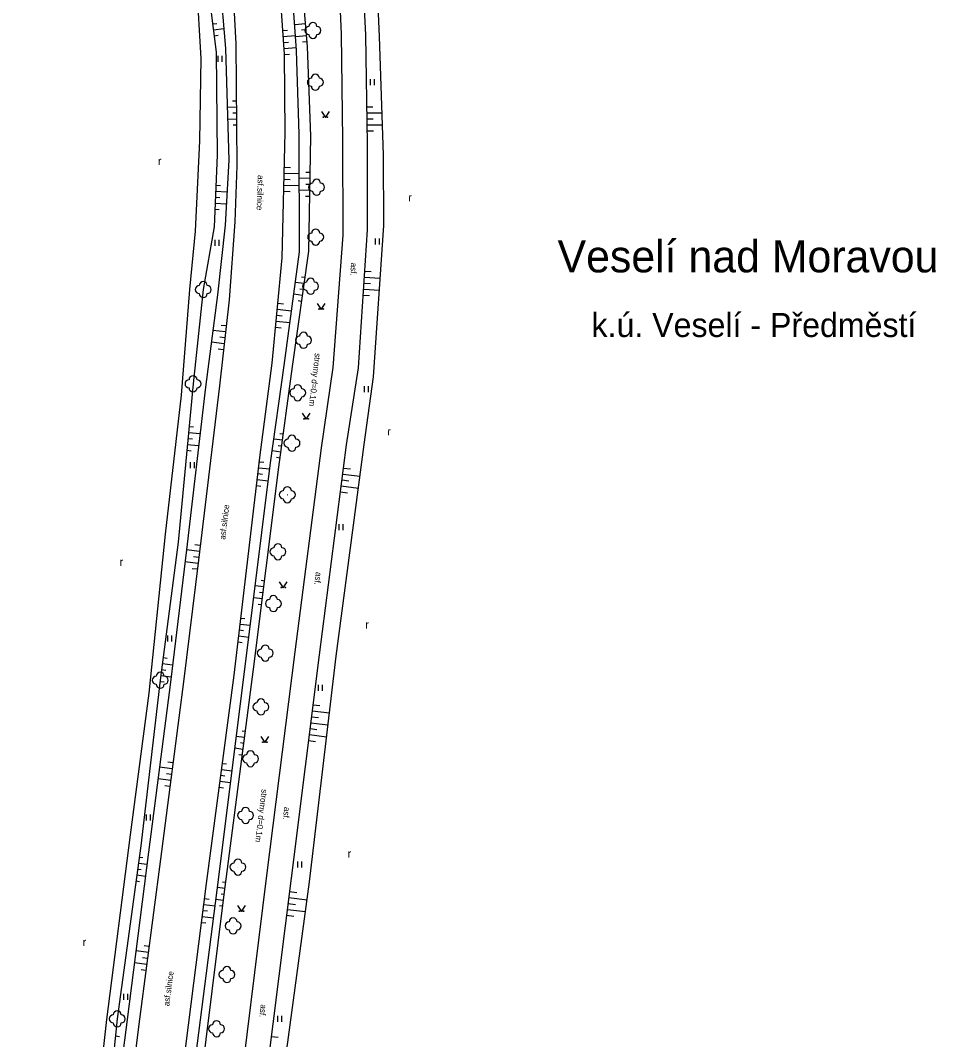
# Model space of a CAD drawing. Extents: x -544674 to -541478, y -1199076 to -1195527.
# Drawn here: x -543649.7 to -543535.3, y -1196121 to -1195993.6 of the extents above; entities that cross this region are included whole.
import ezdxf

# ---------------------------------------------------------------- set-up
doc = ezdxf.new("R2010")
doc.units = 0
for name, color, linetype in [('NÁZEV_K_Ú', 7, 'Continuous'), ('NÁZVY_SÍDEL_JEDNOTKY', 7, 'Continuous'), ('POMOC_POPIS', 7, 'Continuous'), ('ROZHRANÍ_PLOCH', 7, 'Continuous'), ('VÝŠKOPIS', 7, 'Continuous'), ('ZELEŇ', 7, 'Continuous'), ('ZN_KULTUR', 7, 'Continuous')]:
    doc.layers.add(name, color=color, linetype=linetype)

msp = doc.modelspace()

# ---------------------------------------------------------------- linework, layer by layer
at = {"layer": 'ROZHRANÍ_PLOCH'}
for points in [[(-543619.64, -1196131.22), (-543615.81, -1196100.77), (-543612.31, -1196072.88), (-543608.9, -1196046.62), (-543607.43, -1196037.02), (-543606.28, -1196019.77), (-543606.3, -1196009), (-543606.5, -1195995.43), (-543607.06, -1195984.44), (-543608.01, -1195967.52), (-543610.49, -1195940.94), (-543612.66, -1195916.66), (-543613.72, -1195904.08), (-543614, -1195894.09), (-543612.96, -1195887.23), (-543612.45, -1195879.29), (-543612.44, -1195876.36), (-543611.47, -1195876.49), (-543610.1, -1195878.26), (-543608.46, -1195876.99), (-543612.9, -1195869.72), (-543612.98, -1195867.19)], [(-543632.41, -1196211.07), (-543630.37, -1196193.32), (-543624.96, -1196151.17), (-543622.81, -1196132.43), (-543618.85, -1196100.43), (-543615.34, -1196072.49), (-543612.05, -1196046.99), (-543610.57, -1196036.97), (-543609.35, -1196020.42), (-543609.38, -1196008.52), (-543609.53, -1195995.3), (-543610, -1195984.65), (-543611.08, -1195968.31), (-543613.38, -1195942.54), (-543615.71, -1195916.87), (-543616.79, -1195903.73), (-543617.14, -1195895.44), (-543615.68, -1195885.08), (-543615.46, -1195880.81), (-543615.95, -1195868.23)], [(-543632.46, -1195882.95), (-543630.66, -1195904.04), (-543629.59, -1195915.71), (-543627.44, -1195938.51), (-543625.46, -1195962.01), (-543624.21, -1195975.84), (-543623.14, -1195988.77), (-543622.74, -1195996.52), (-543622.61, -1196011.77), (-543622.88, -1196018.77), (-543623.58, -1196028.52), (-543624.79, -1196039.27), (-543627.41, -1196061.04), (-543629.27, -1196076.23), (-543632.15, -1196098.41), (-543634.76, -1196118.38), (-543637.1, -1196136.86), (-543638.96, -1196152.81), (-543641.47, -1196173.25), (-543643.67, -1196191.48), (-543644.99, -1196202.76)], [(-543639.09, -1196203.64), (-543635.02, -1196171.2), (-543630.55, -1196134.22), (-543626.42, -1196101.45), (-543622.95, -1196075.4), (-543619.74, -1196048.22), (-543618.21, -1196036.42), (-543616.96, -1196023.24), (-543616.56, -1196007.59), (-543616.68, -1195997.82), (-543617.53, -1195985.22), (-543618.61, -1195971.27), (-543620.62, -1195946.9), (-543623.05, -1195920.62), (-543624.43, -1195906.58), (-543625.23, -1195895.93), (-543626.38, -1195882.3)]]:
    msp.add_lwpolyline(points, dxfattribs=at)
at = {"layer": 'VÝŠKOPIS'}
for points in [[(-543637.68, -1196204.91), (-543633.55, -1196170.77), (-543629.08, -1196133.41), (-543625.09, -1196102.26), (-543621.67, -1196075.01), (-543618.41, -1196048.88), (-543616.7, -1196036.73), (-543614.81, -1196022.52), (-543614.82, -1196007.8), (-543615.15, -1195997.35), (-543616.06, -1195985.01), (-543617.47, -1195971.56), (-543619.73, -1195946.13), (-543622.24, -1195919.83), (-543623.14, -1195907.11), (-543624.18, -1195895.5), (-543625.31, -1195882.76)], [(-543637.05, -1196204.96), (-543632.44, -1196170.19), (-543627.94, -1196133.03), (-543624.22, -1196102.84), (-543620.55, -1196074.64), (-543617.37, -1196049.43), (-543615.66, -1196036.82), (-543613.64, -1196022.43), (-543613.38, -1196008.04), (-543613.8, -1195996.84), (-543614.79, -1195985), (-543616.24, -1195972.22), (-543618.58, -1195945.75), (-543620.93, -1195921.24), (-543621.68, -1195907.9), (-543622.76, -1195895.51), (-543624.24, -1195883.03)], [(-543633.79, -1195883.63), (-543632.32, -1195903.25), (-543630.88, -1195916.7), (-543629.01, -1195937.51), (-543627.31, -1195961.18), (-543625.83, -1195976.22), (-543624.72, -1195988.72), (-543624.05, -1195997.08), (-543623.61, -1196011.03), (-543624.09, -1196019.16), (-543625.02, -1196027.87), (-543626.53, -1196039.42), (-543628.92, -1196059.75), (-543630.9, -1196076.27), (-543633.64, -1196097.53), (-543636.3, -1196118.46), (-543638.55, -1196135.87), (-543640.73, -1196153.47), (-543642.99, -1196172.25), (-543645.26, -1196191.46), (-543646.43, -1196201.58)], [(-543635.11, -1195884.59), (-543633.71, -1195902.59), (-543632.22, -1195917.58), (-543630.51, -1195936.95), (-543628.32, -1195960.9), (-543627.16, -1195976.56), (-543626.29, -1195988.96), (-543625.18, -1195997.54), (-543625.08, -1196010.41), (-543625.45, -1196019.37), (-543626.81, -1196027.23), (-543628.09, -1196039), (-543629.96, -1196058.78), (-543632.18, -1196076.05), (-543634.6, -1196096.72), (-543637.55, -1196118.36), (-543639.29, -1196135.15), (-543642.06, -1196154.03), (-543643.93, -1196171.42), (-543646.59, -1196191.4), (-543647.93, -1196200.94)], [(-543625.64, -1195994.02), (-543625.1, -1195993.95)], [(-543625.54, -1195994.77), (-543624.25, -1195994.6)], [(-543616.88, -1195994.84), (-543616.27, -1195994.8)], [(-543614.04, -1195994.03), (-543615.39, -1195994.14)], [(-543613.97, -1195994.77), (-543614.52, -1195994.82)], [(-543625.44, -1195995.51), (-543624.94, -1195995.44)], [(-543616.83, -1195995.59), (-543615.29, -1195995.48)], [(-543616.78, -1195996.33), (-543616.16, -1195996.29)], [(-543613.91, -1195995.52), (-543615.28, -1195995.64)], [(-543613.85, -1195996.27), (-543614.4, -1195996.32)], [(-543616.73, -1195997.08), (-543615.18, -1195996.98)], [(-543616.68, -1195997.83), (-543616.06, -1195997.82)], [(-543622.68, -1196003.69), (-543623.14, -1196003.69)], [(-543622.67, -1196004.44), (-543623.82, -1196004.45)], [(-543622.67, -1196005.19), (-543623.12, -1196005.19)], [(-543606.37, -1196004.4), (-543605.62, -1196004.39)], [(-543606.36, -1196005.15), (-543604.48, -1196005.12)], [(-543622.66, -1196005.94), (-543623.77, -1196005.95)], [(-543606.35, -1196005.9), (-543605.59, -1196005.89)], [(-543606.33, -1196006.65), (-543604.43, -1196006.62)], [(-543622.65, -1196006.69), (-543623.09, -1196006.69)], [(-543606.32, -1196007.4), (-543605.56, -1196007.39)], [(-543616.69, -1196012.68), (-543614.82, -1196012.73)], [(-543616.67, -1196011.93), (-543615.93, -1196011.95)], [(-543613.46, -1196012.59), (-543614, -1196012.58)], [(-543625.24, -1196014.19), (-543624.66, -1196014.21)], [(-543616.73, -1196014.18), (-543614.82, -1196014.23)], [(-543616.71, -1196013.43), (-543615.95, -1196013.45)], [(-543613.48, -1196013.34), (-543614.82, -1196013.31)], [(-543613.49, -1196014.09), (-543614.02, -1196014.08)], [(-543625.27, -1196014.94), (-543623.84, -1196015)], [(-543616.75, -1196014.93), (-543615.97, -1196014.95)], [(-543613.5, -1196014.84), (-543614.82, -1196014.81)], [(-543613.52, -1196015.59), (-543614.04, -1196015.58)], [(-543625.33, -1196016.44), (-543623.93, -1196016.5)], [(-543625.3, -1196015.69), (-543624.73, -1196015.71)], [(-543625.36, -1196017.19), (-543624.81, -1196017.21)], [(-543614.1, -1196025.73), (-543614.55, -1196025.67)], [(-543606.67, -1196025.66), (-543604.7, -1196025.79)], [(-543606.62, -1196024.91), (-543605.83, -1196024.96)], [(-543614.21, -1196026.47), (-543615.32, -1196026.32)], [(-543606.72, -1196026.4), (-543605.93, -1196026.46)], [(-543614.42, -1196027.96), (-543615.51, -1196027.8)], [(-543614.31, -1196027.22), (-543614.75, -1196027.15)], [(-543606.82, -1196027.9), (-543606.04, -1196027.95)], [(-543606.77, -1196027.15), (-543604.8, -1196027.28)], [(-543617.5, -1196028.94), (-543616.78, -1196029.01)], [(-543614.52, -1196028.7), (-543614.96, -1196028.64)], [(-543617.64, -1196030.44), (-543616.94, -1196030.5)], [(-543617.57, -1196029.69), (-543615.79, -1196029.86)], [(-543623.94, -1196031.76), (-543624.57, -1196031.69)], [(-543617.78, -1196031.93), (-543617.1, -1196031.99)], [(-543617.71, -1196031.18), (-543615.98, -1196031.35)], [(-543624.03, -1196032.5), (-543625.6, -1196032.33)], [(-543624.11, -1196033.25), (-543624.75, -1196033.18)], [(-543624.2, -1196033.99), (-543625.8, -1196033.81)], [(-543624.28, -1196034.74), (-543624.93, -1196034.67)], [(-543628.59, -1196044.33), (-543628.01, -1196044.38)], [(-543628.73, -1196045.82), (-543628.16, -1196045.87)], [(-543628.66, -1196045.07), (-543627.21, -1196045.21)], [(-543616.91, -1196046.05), (-543617.99, -1196045.9)], [(-543616.81, -1196045.3), (-543617.24, -1196045.25)], [(-543628.88, -1196047.31), (-543628.31, -1196047.37)], [(-543628.81, -1196046.57), (-543627.39, -1196046.7)], [(-543617.11, -1196047.53), (-543618.2, -1196047.39)], [(-543617.01, -1196046.79), (-543617.45, -1196046.73)], [(-543617.21, -1196048.28), (-543617.65, -1196048.22)], [(-543619.89, -1196049.48), (-543618.5, -1196049.64)], [(-543619.8, -1196048.73), (-543619.25, -1196048.8)], [(-543609.28, -1196049.52), (-543608.42, -1196049.63)], [(-543620.06, -1196050.97), (-543618.69, -1196051.13)], [(-543619.98, -1196050.22), (-543619.42, -1196050.29)], [(-543609.47, -1196051.01), (-543608.61, -1196051.12)], [(-543609.37, -1196050.27), (-543607.23, -1196050.55)], [(-543620.15, -1196051.71), (-543619.6, -1196051.78)], [(-543609.66, -1196052.5), (-543608.81, -1196052.61)], [(-543609.57, -1196051.75), (-543607.43, -1196052.03)], [(-543627.28, -1196059.95), (-543628.92, -1196059.75)], [(-543627.19, -1196059.2), (-543627.85, -1196059.12)], [(-543627.46, -1196061.44), (-543629.1, -1196061.24)], [(-543627.37, -1196060.69), (-543628.02, -1196060.61)], [(-543627.55, -1196062.18), (-543628.2, -1196062.1)], [(-543619.16, -1196063.65), (-543619.59, -1196063.59)], [(-543619.26, -1196064.39), (-543620.33, -1196064.26)], [(-543619.35, -1196065.14), (-543619.78, -1196065.08)], [(-543619.45, -1196065.88), (-543620.51, -1196065.75)], [(-543619.54, -1196066.63), (-543619.97, -1196066.57)], [(-543622.2, -1196069.02), (-543620.94, -1196069.17)], [(-543622.11, -1196068.28), (-543621.6, -1196068.33)], [(-543622.28, -1196069.76), (-543621.78, -1196069.82)], [(-543622.46, -1196071.25), (-543621.96, -1196071.31)], [(-543622.37, -1196070.51), (-543621.13, -1196070.66)], [(-543631.91, -1196073.97), (-543630.64, -1196074.13)], [(-543631.82, -1196073.22), (-543631.31, -1196073.29)], [(-543632.01, -1196074.71), (-543631.5, -1196074.78)], [(-543632.2, -1196076.2), (-543631.68, -1196076.26)], [(-543632.1, -1196075.46), (-543630.82, -1196075.62)], [(-543613.09, -1196079.11), (-543612.25, -1196079.22)], [(-543613.19, -1196079.86), (-543611.06, -1196080.12)], [(-543613.37, -1196081.35), (-543611.24, -1196081.61)], [(-543613.28, -1196080.6), (-543612.43, -1196080.71)], [(-543621.66, -1196083.19), (-543622.68, -1196083.06)], [(-543621.57, -1196082.44), (-543621.97, -1196082.39)], [(-543613.56, -1196082.83), (-543611.41, -1196083.1)], [(-543613.47, -1196082.09), (-543612.61, -1196082.2)], [(-543621.76, -1196083.93), (-543622.16, -1196083.88)], [(-543613.65, -1196083.58), (-543612.79, -1196083.69)], [(-543621.86, -1196084.68), (-543622.87, -1196084.54)], [(-543621.95, -1196085.42), (-543622.36, -1196085.37)], [(-543630.68, -1196087.1), (-543632.27, -1196086.89)], [(-543630.58, -1196086.36), (-543631.22, -1196086.27)], [(-543624.42, -1196086.44), (-543623.9, -1196086.51)], [(-543630.78, -1196087.84), (-543631.41, -1196087.76)], [(-543624.62, -1196087.92), (-543624.1, -1196087.99)], [(-543624.52, -1196087.18), (-543623.22, -1196087.35)], [(-543630.87, -1196088.59), (-543632.46, -1196088.38)], [(-543630.97, -1196089.33), (-543631.61, -1196089.25)], [(-543624.82, -1196089.41), (-543624.29, -1196089.48)], [(-543624.72, -1196088.67), (-543623.41, -1196088.84)], [(-543634.8, -1196098.15), (-543634.37, -1196098.21)], [(-543635, -1196099.64), (-543634.57, -1196099.7)], [(-543634.9, -1196098.89), (-543633.83, -1196099.04)], [(-543635.1, -1196100.38), (-543634.02, -1196100.53)], [(-543635.2, -1196101.12), (-543634.77, -1196101.18)], [(-543624.12, -1196102.06), (-543625.05, -1196101.94)], [(-543624.02, -1196101.32), (-543624.4, -1196101.27)], [(-543626.66, -1196103.32), (-543626.09, -1196103.39)], [(-543624.31, -1196103.55), (-543625.24, -1196103.43)], [(-543624.22, -1196102.8), (-543624.59, -1196102.76)], [(-543616.11, -1196103.19), (-543613.84, -1196103.48)], [(-543616.02, -1196102.45), (-543615.11, -1196102.56)], [(-543626.75, -1196104.06), (-543625.34, -1196104.24)], [(-543624.4, -1196104.29), (-543624.77, -1196104.25)], [(-543616.3, -1196104.68), (-543614.04, -1196104.96)], [(-543616.21, -1196103.94), (-543615.3, -1196104.05)], [(-543626.94, -1196105.55), (-543625.53, -1196105.73)], [(-543626.84, -1196104.81), (-543626.28, -1196104.88)], [(-543616.4, -1196105.42), (-543615.49, -1196105.54)], [(-543627.03, -1196106.3), (-543626.47, -1196106.37)], [(-543633.58, -1196109.33), (-543634.19, -1196109.25)], [(-543633.67, -1196110.07), (-543635.21, -1196109.87)], [(-543633.77, -1196110.82), (-543634.38, -1196110.74)], [(-543633.87, -1196111.56), (-543635.4, -1196111.36)], [(-543633.97, -1196112.3), (-543634.58, -1196112.22)], [(-543637.77, -1196120.5), (-543637.29, -1196120.55)], [(-543618.3, -1196120.55), (-543617.45, -1196120.66)]]:
    msp.add_lwpolyline(points, dxfattribs=at)
at = {"layer": 'ZELEŇ'}
for points in [[(-543637.49, -1195885.85), (-543636.25, -1195900.75), (-543634.27, -1195918.95), (-543632.55, -1195936.22), (-543630.06, -1195959.48), (-543628.32, -1195978.08), (-543627.64, -1195989.06), (-543627.13, -1195998.35), (-543627.3, -1196008.65), (-543627.81, -1196019.91), (-543628.52, -1196027.23), (-543629.59, -1196040.43), (-543631.56, -1196057.77), (-543633.61, -1196077.67), (-543635.95, -1196095.36), (-543638.88, -1196118.45), (-543640.59, -1196133.76), (-543643.14, -1196154.34), (-543645.07, -1196170.53), (-543648, -1196190.91), (-543649.65, -1196200.28)], [(-543620.94, -1196214.98), (-543624.31, -1196211.9), (-543626.03, -1196206.25), (-543625.47, -1196195.96), (-543620.17, -1196152.27), (-543617.52, -1196130.8), (-543613.54, -1196101.25), (-543610.23, -1196073.03), (-543606.7, -1196046.58), (-543605.55, -1196038.14), (-543604.25, -1196019.22), (-543604.31, -1196010.39), (-543604.8, -1195995.59), (-543605.27, -1195985.05), (-543606.35, -1195966.98), (-543608.76, -1195939.98), (-543609.96, -1195918.4), (-543608.87, -1195913.01), (-543606.32, -1195907.39), (-543600.46, -1195896.38), (-543598.68, -1195894.64), (-543593.62, -1195901.24), (-543585.09, -1195909.68)]]:
    msp.add_lwpolyline(points, dxfattribs=at)
for centre in [(-543613.11, -1195994.84), (-543612.81, -1196001.31), (-543612.65, -1196014.44), (-543612.77, -1196020.66), (-543613.4, -1196026.81), (-543626.81, -1196027.23), (-543614.29, -1196033.55), (-543628.09, -1196039), (-543615.01, -1196040.11), (-543615.73, -1196046.42), (-543616.31, -1196052.86), (-543617.48, -1196059.98), (-543618.04, -1196066.47), (-543619.07, -1196072.65), (-543632.18, -1196076.05), (-543619.61, -1196079.38), (-543620.91, -1196085.85), (-543621.53, -1196092.93), (-543622.48, -1196099.39), (-543623.08, -1196106.74), (-543623.85, -1196112.82), (-543637.55, -1196118.36), (-543625.15, -1196119.59)]:
    msp.add_circle(centre, 0.0005, dxfattribs=at)
for centre, start, end in [((-543613.11, -1195994.34), 0, 179.99999), ((-543613.61, -1195994.84), 89.99999, 269.99999), ((-543612.61, -1195994.84), 270, 89.99999), ((-543613.11, -1195995.34), 179.99999, 359.99999), ((-543613.31, -1196001.31), 89.99999, 269.99999), ((-543612.81, -1196000.81), 0, 179.99999), ((-543612.31, -1196001.31), 270, 89.99999), ((-543612.81, -1196001.81), 179.99999, 359.99999), ((-543613.15, -1196014.44), 89.99999, 269.99999), ((-543612.65, -1196013.94), 0, 179.99999), ((-543612.15, -1196014.44), 270, 89.99999), ((-543612.65, -1196014.94), 179.99999, 359.99999), ((-543613.27, -1196020.66), 89.99999, 269.99999), ((-543612.77, -1196020.16), 0, 179.99999), ((-543612.27, -1196020.66), 270, 89.99999), ((-543612.77, -1196021.16), 179.99999, 359.99999), ((-543627.31, -1196027.23), 89.99999, 269.99999), ((-543626.81, -1196026.73), 0, 179.99999), ((-543626.31, -1196027.23), 270, 89.99999), ((-543613.9, -1196026.81), 89.99999, 269.99999), ((-543613.4, -1196026.31), 0, 179.99999), ((-543612.9, -1196026.81), 270, 89.99999), ((-543626.81, -1196027.73), 179.99999, 359.99999), ((-543613.4, -1196027.31), 179.99999, 359.99999), ((-543614.79, -1196033.55), 89.99999, 269.99999), ((-543614.29, -1196033.05), 0, 179.99999), ((-543613.79, -1196033.55), 270, 89.99999), ((-543614.29, -1196034.05), 179.99999, 359.99999), ((-543628.59, -1196039), 89.99999, 269.99999), ((-543628.09, -1196038.5), 0, 179.99999), ((-543627.59, -1196039), 270, 89.99999), ((-543628.09, -1196039.5), 179.99999, 359.99999), ((-543615.51, -1196040.11), 89.99999, 269.99999), ((-543615.01, -1196039.61), 0, 179.99999), ((-543614.51, -1196040.11), 270, 89.99999), ((-543615.01, -1196040.61), 179.99999, 359.99999), ((-543616.23, -1196046.42), 89.99999, 269.99999), ((-543615.73, -1196045.92), 0, 179.99999), ((-543615.23, -1196046.42), 270, 89.99999), ((-543615.73, -1196046.92), 179.99999, 359.99999), ((-543616.81, -1196052.86), 89.99999, 269.99999), ((-543616.31, -1196052.36), 0, 179.99999), ((-543615.81, -1196052.86), 270, 89.99999), ((-543616.31, -1196053.36), 179.99999, 359.99999), ((-543617.98, -1196059.98), 89.99999, 269.99999), ((-543617.48, -1196059.48), 0, 179.99999), ((-543616.98, -1196059.98), 270, 89.99999), ((-543617.48, -1196060.48), 179.99999, 359.99999), ((-543618.54, -1196066.47), 89.99999, 269.99999), ((-543618.04, -1196065.97), 0, 179.99999), ((-543617.54, -1196066.47), 270, 89.99999), ((-543618.04, -1196066.97), 179.99999, 359.99999), ((-543619.57, -1196072.65), 89.99999, 269.99999), ((-543619.07, -1196072.15), 0, 179.99999), ((-543618.57, -1196072.65), 270, 89.99999), ((-543619.07, -1196073.15), 179.99999, 359.99999), ((-543632.18, -1196075.55), 0, 179.99999), ((-543632.68, -1196076.05), 89.99999, 269.99999), ((-543632.18, -1196076.55), 179.99999, 359.99999), ((-543631.68, -1196076.05), 270, 89.99999), ((-543620.11, -1196079.38), 89.99999, 269.99999), ((-543619.61, -1196078.88), 0, 179.99999), ((-543619.11, -1196079.38), 270, 89.99999), ((-543619.61, -1196079.88), 179.99999, 359.99999), ((-543621.41, -1196085.85), 89.99999, 269.99999), ((-543620.91, -1196085.35), 0, 179.99999), ((-543620.41, -1196085.85), 270, 89.99999), ((-543620.91, -1196086.35), 179.99999, 359.99999), ((-543621.53, -1196092.43), 0, 179.99999), ((-543622.03, -1196092.93), 89.99999, 269.99999), ((-543621.03, -1196092.93), 270, 89.99999), ((-543621.53, -1196093.43), 179.99999, 359.99999), ((-543622.98, -1196099.39), 89.99999, 269.99999), ((-543622.48, -1196098.89), 0, 179.99999), ((-543621.98, -1196099.39), 270, 89.99999), ((-543622.48, -1196099.89), 179.99999, 359.99999), ((-543623.08, -1196106.24), 0, 179.99999), ((-543623.58, -1196106.74), 89.99999, 269.99999), ((-543623.08, -1196107.24), 179.99999, 359.99999), ((-543622.58, -1196106.74), 270, 89.99999), ((-543624.35, -1196112.82), 89.99999, 269.99999), ((-543623.85, -1196112.32), 0, 179.99999), ((-543623.35, -1196112.82), 270, 89.99999), ((-543623.85, -1196113.32), 179.99999, 359.99999), ((-543637.55, -1196117.86), 0, 179.99999), ((-543638.05, -1196118.36), 89.99999, 269.99999), ((-543637.05, -1196118.36), 270, 89.99999), ((-543625.15, -1196119.09), 0, 179.99999), ((-543637.55, -1196118.86), 179.99999, 359.99999), ((-543625.65, -1196119.59), 89.99999, 269.99999), ((-543624.65, -1196119.59), 270, 89.99999), ((-543625.15, -1196120.09), 179.99999, 359.99999)]:
    msp.add_arc(centre, 0.5, start, end, dxfattribs=at)
at = {"layer": 'ZN_KULTUR'}
for p, q in [((-543624.94, -1195998.765), (-543624.94, -1195998.015)), ((-543624.44, -1195998.765), (-543624.44, -1195998.015)), ((-543605.91, -1196001.695), (-543605.91, -1196000.945)), ((-543605.41, -1196001.695), (-543605.41, -1196000.945)), ((-543625.34, -1196021.765), (-543625.34, -1196021.015)), ((-543624.84, -1196021.765), (-543624.84, -1196021.015)), ((-543605.31, -1196021.595), (-543605.31, -1196020.845)), ((-543604.81, -1196021.595), (-543604.81, -1196020.845)), ((-543606.69, -1196040.055), (-543606.69, -1196039.305)), ((-543606.19, -1196040.055), (-543606.19, -1196039.305)), ((-543628.42, -1196049.555), (-543628.42, -1196048.805)), ((-543627.92, -1196049.555), (-543627.92, -1196048.805)), ((-543609.84, -1196057.275), (-543609.84, -1196056.525)), ((-543609.34, -1196057.275), (-543609.34, -1196056.525)), ((-543631.23, -1196071.215), (-543631.23, -1196070.465)), ((-543630.73, -1196071.215), (-543630.73, -1196070.465)), ((-543612.4, -1196077.375), (-543612.4, -1196076.625)), ((-543611.9, -1196077.375), (-543611.9, -1196076.625)), ((-543633.91, -1196093.575), (-543633.91, -1196092.825)), ((-543633.41, -1196093.575), (-543633.41, -1196092.825)), ((-543614.99, -1196099.435), (-543614.99, -1196098.685)), ((-543614.49, -1196099.435), (-543614.49, -1196098.685)), ((-543636.72, -1196115.985), (-543636.72, -1196115.235)), ((-543636.22, -1196115.985), (-543636.22, -1196115.235)), ((-543617.5, -1196118.725), (-543617.5, -1196117.975)), ((-543617, -1196118.725), (-543617, -1196117.975))]:
    msp.add_line(p, q, dxfattribs=at)
for points in [[(-543612.06, -1196004.97), (-543611.56, -1196005.72), (-543611.06, -1196004.97)], [(-543612.59, -1196028.95), (-543612.09, -1196029.7), (-543611.59, -1196028.95)], [(-543614.47, -1196042.67), (-543613.97, -1196043.42), (-543613.47, -1196042.67)], [(-543617.31, -1196063.76), (-543616.81, -1196064.51), (-543616.31, -1196063.76)], [(-543619.62, -1196083.07), (-543619.12, -1196083.82), (-543618.62, -1196083.07)], [(-543622.54, -1196104.21), (-543622.04, -1196104.96), (-543621.54, -1196104.21)]]:
    msp.add_lwpolyline(points, dxfattribs=at)
for centre in [(-543611.81, -1196005.67), (-543611.31, -1196005.67), (-543612.34, -1196029.65), (-543611.84, -1196029.65), (-543614.22, -1196043.37), (-543613.72, -1196043.37), (-543617.06, -1196064.46), (-543616.56, -1196064.46), (-543619.37, -1196083.77), (-543618.87, -1196083.77), (-543622.29, -1196104.91), (-543621.79, -1196104.91)]:
    msp.add_circle(centre, 0.05, dxfattribs=at)

# ---------------------------------------------------------------- texts
at = {"layer": 'NÁZEV_K_Ú'}
msp.add_text('k.ú. Veselí - Předměstí', height=3, dxfattribs=at).set_placement((-543578.32, -1196033.15))
at = {"layer": 'NÁZVY_SÍDEL_JEDNOTKY'}
msp.add_text('Veselí nad Moravou', height=4, dxfattribs=at).set_placement((-543582.56, -1196025.07))
at = {"layer": 'POMOC_POPIS'}
for s, rotation, p in [('asf.silnice', 268.00924, (-543619.99, -1196012.9)), ('asf.', 267.54218, (-543608.36, -1196023.85)), ('asf.silnice', 83.26448, (-543624.06, -1196058.5)), ('asf.', 262.64833, (-543612.74, -1196062.48)), ('asf.', 262.83965, (-543616.68, -1196091.83)), ('asf.silnice', 82.62594, (-543631.06, -1196116.81)), ('asf.', 262.94551, (-543619.62, -1196116.53))]:
    msp.add_text(s, height=0.75, rotation=rotation, dxfattribs=at).set_placement(p)
at = {"layer": 'ZELEŇ'}
for rotation, p in [(263.47699, (-543612.86, -1196035.14)), (263.01199, (-543619.51, -1196089.63))]:
    msp.add_text('stromy d=0.1m', height=0.75, rotation=rotation, dxfattribs=at).set_placement(p)
at = {"layer": 'ZN_KULTUR'}
for p in [(-543632.468, -1196011.652), (-543601.218, -1196016.212), (-543603.838, -1196045.452), (-543637.258, -1196061.762), (-543606.558, -1196069.582), (-543608.788, -1196098.212), (-543641.868, -1196109.262)]:
    msp.add_text('r', height=1, dxfattribs=at).set_placement(p)

doc.saveas('drawing.dxf')
